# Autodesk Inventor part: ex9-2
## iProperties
Shininess: 64.0
Length Units: 11272
Angle Units: 11279
Time Units: 11290
Mass Units: 11286
Length Display Precision: 3
Angle Display Precision: 2
Compacted: True
Part Number: ex9-2
Document SubType Name: Sheet Metal
Created: 2002-11
Designer: Elise Moss
Density: 0.0
Volumn: 0.0
Area: 0.0
PropertySet Name: Model Information
Control State: 0
Master: False
Checked Out: False
Author: Elise Moss
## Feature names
1. Plate1
2. Bend1
3. Cut1
